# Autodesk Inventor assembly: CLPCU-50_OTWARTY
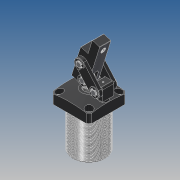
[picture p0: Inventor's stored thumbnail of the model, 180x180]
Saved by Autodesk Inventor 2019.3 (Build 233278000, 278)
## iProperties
Created: 2010-03
Part Number: CLPCU-50_OTWARTY
Material: Ogólny
Document SubType Name: Assembly
Designer: CADENGINEERING4
Sending System: PRO/ENGINEER BY PARAMETRIC TECHNOLOGY CORPORATION, 2007170
Preprocessor: PRO/ENGINEER BY PARAMETRIC TECHNOLOGY CORPORATION, 2007170
Title: CPLCU-50_ASM
Author: Administrator
Revision Number: 2LAST_VERSION
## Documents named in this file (10)
- E:\SERWER_ZAPAS\MODELE brakujace\PNEUMATIC\CPLCU(STEP)\cplcu-50_asm\CLPCU-50_OTWARTY.iam
- E:\SERWER_ZAPAS\MODELE brakujace\PNEUMATIC\CPLCU(STEP)\cplcu-50_asm\CPLCU-50-07.ipt
- E:\SERWER_ZAPAS\MODELE brakujace\PNEUMATIC\CPLCU(STEP)\cplcu-50_asm\CPLCU-50-05.ipt
- E:\SERWER_ZAPAS\MODELE brakujace\PNEUMATIC\CPLCU(STEP)\cplcu-50_asm\CPLCU-50-06.ipt
- E:\SERWER_ZAPAS\MODELE brakujace\PNEUMATIC\CPLCU(STEP)\cplcu-50_asm\CPLCU-50-01.ipt
- E:\SERWER_ZAPAS\MODELE brakujace\PNEUMATIC\CPLCU(STEP)\cplcu-50_asm\CPLCU-50-02.ipt
- E:\SERWER_ZAPAS\MODELE brakujace\PNEUMATIC\CPLCU(STEP)\cplcu-50_asm\CPLCU-50-08.ipt
- E:\SERWER_ZAPAS\MODELE brakujace\PNEUMATIC\CPLCU(STEP)\cplcu-50_asm\CPLCU-50-03.ipt
- E:\SERWER_ZAPAS\MODELE brakujace\PNEUMATIC\CPLCU(STEP)\cplcu-50_asm\CPLCU-50-04.ipt
- E:\SERWER_ZAPAS\MODELE brakujace\PNEUMATIC\CPLCU(STEP)\cplcu-50_asm\CPLCU-50-09.ipt
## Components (21 placed, 21 different names)
1. CPLCU-50-07_0 — Zestawiające:25, Zestawiające:26
2. CPLCU-50-05_1 — Zestawiające:1, Zestawiające:2
3. CPLCU-50-06_2 — Zestawiające:15, Zestawiające:16, Zestawiające:17, Zestawiające:18, Zestawiające:22, Zestawiające:25, Zestawiające:26
4. CPLCU-50-01_3 — Zestawiające:21, Zestawiające:22, Zestawiające:23, Zestawiające:24
5. CPLCU-50-02_4 — Zestawiające:1, Zestawiające:3, Zestawiające:4, Zestawiające:10
6. CPLCU-50-02_5 — Zestawiające:2, Zestawiające:3, Zestawiające:4, Zestawiające:5, Zestawiające:24
7. CPLCU-50-08_6 — Zestawiające:15, Zestawiające:17
8. CPLCU-50-08_7 — Zestawiające:6, Zestawiające:9
9. CPLCU-50-08_8
10. CPLCU-50-08_9 — Zestawiające:16, Zestawiające:18, Zestawiające:19, Zestawiające:20, Zestawiające:21
11. CPLCU-50-08_10 — Zestawiające:5
12. CPLCU-50-08_11 — Zestawiające:7, Zestawiające:8
13. CPLCU-50-03_12 — Równoległe:5, Równoległe:6, Zestawiające:13, Zestawiające:14, Zestawiające:19
14. CPLCU-50-04_13 — Równoległe:1, Równoległe:4, Zestawiające:6, Zestawiające:7, Zestawiające:10, Zestawiające:11, Zestawiające:12, Zestawiające:23
15. CPLCU-50-04_14 — Równoległe:1, Równoległe:4
16. CPLCU-50-09_15 — Równoległe:6, Zestawiające:13
17. CPLCU-50-09_16 — Równoległe:5, Zestawiające:14, Zestawiające:20
18. CPLCU-50-09_17 — Równoległe:3, Zestawiające:9, Zestawiające:11
19. CPLCU-50-09_18 — Równoległe:2, Zestawiające:8, Zestawiające:12
20. CPLCU-50-09_19 — Równoległe:3
21. CPLCU-50-09_20 — Równoległe:2
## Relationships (32: Mate 26, Flush 6)
- Równoległe:1 [Flush]: CPLCU-50-04_13 ↔ CPLCU-50-04_14
- Równoległe:2 [Flush]: CPLCU-50-09_18 ↔ CPLCU-50-09_20
- Równoległe:3 [Flush]: CPLCU-50-09_17 ↔ CPLCU-50-09_19
- Równoległe:4 [Flush]: CPLCU-50-04_13 ↔ CPLCU-50-04_14
- Zestawiające:1 [Mate]: CPLCU-50-05_1 ↔ CPLCU-50-02_4
- Zestawiające:2 [Mate]: CPLCU-50-05_1 ↔ CPLCU-50-02_5
- Zestawiające:3 [Mate]: CPLCU-50-02_4 ↔ CPLCU-50-02_5
- Zestawiające:4 [Mate]: CPLCU-50-02_4 ↔ CPLCU-50-02_5
- Zestawiające:5 [Mate]: CPLCU-50-02_5 ↔ CPLCU-50-08_10
- Zestawiające:6 [Mate]: CPLCU-50-08_7 ↔ CPLCU-50-04_13
- Zestawiające:7 [Mate]: CPLCU-50-08_11 ↔ CPLCU-50-04_13
- Zestawiające:8 [Mate]: CPLCU-50-08_11 ↔ CPLCU-50-09_18
- Zestawiające:9 [Mate]: CPLCU-50-08_7 ↔ CPLCU-50-09_17
- Zestawiające:10 [Mate]: CPLCU-50-02_4 ↔ CPLCU-50-04_13
- Zestawiające:11 [Mate]: CPLCU-50-04_13 ↔ CPLCU-50-09_17
- Zestawiające:12 [Mate]: CPLCU-50-04_13 ↔ CPLCU-50-09_18
- Równoległe:5 [Flush]: CPLCU-50-03_12 ↔ CPLCU-50-09_16
- Równoległe:6 [Flush]: CPLCU-50-03_12 ↔ CPLCU-50-09_15
- Zestawiające:13 [Mate]: CPLCU-50-03_12 ↔ CPLCU-50-09_15
- Zestawiające:14 [Mate]: CPLCU-50-03_12 ↔ CPLCU-50-09_16
- Zestawiające:15 [Mate]: CPLCU-50-06_2 ↔ CPLCU-50-08_6
- Zestawiające:16 [Mate]: CPLCU-50-06_2 ↔ CPLCU-50-08_9
- Zestawiające:17 [Mate]: CPLCU-50-06_2 ↔ CPLCU-50-08_6
- Zestawiające:18 [Mate]: CPLCU-50-06_2 ↔ CPLCU-50-08_9
- Zestawiające:19 [Mate]: CPLCU-50-08_9 ↔ CPLCU-50-03_12
- Zestawiające:20 [Mate]: CPLCU-50-08_9 ↔ CPLCU-50-09_16
- Zestawiające:21 [Mate]: CPLCU-50-01_3 ↔ CPLCU-50-08_9
- Zestawiające:22 [Mate]: CPLCU-50-06_2 ↔ CPLCU-50-01_3
- Zestawiające:23 [Mate]: CPLCU-50-01_3 ↔ CPLCU-50-04_13
- Zestawiające:24 [Mate]: CPLCU-50-01_3 ↔ CPLCU-50-02_5
- Zestawiające:25 [Mate]: CPLCU-50-07_0 ↔ CPLCU-50-06_2
- Zestawiające:26 [Mate]: CPLCU-50-07_0 ↔ CPLCU-50-06_2
